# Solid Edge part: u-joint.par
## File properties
Title: Ypke
Author: Abhinav Rai
Template: normal.par
Last saved by: Cadcim
Revision: 8
Application: Solid Edge
Density: 0.0000078 kg/mm^3
Accuracy: 0.01
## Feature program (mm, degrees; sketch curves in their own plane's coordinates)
sketch for "unnamed Protrusion 1" plane through (0, 0, 0) normal (0, -1, 0) x-axis (1, 0, 0)
  line (-44.45, -33.7976) -> (-44.45, 4.3024)
  arc centre (0, 4.3024) radius 44.45 from (-44.45, 4.3024) to (44.45, 4.3024) cw
  line (44.45, 4.3024) -> (44.45, -33.7976)
  line (44.45, -33.7976) -> (25.4, -33.7976)
  line (25.4, -33.7976) -> (25.4, 4.3024)
  arc centre (0, 4.3024) radius 25.4 from (-25.4, 4.3024) to (25.4, 4.3024) cw
  line (-25.4, -33.7976) -> (-25.4, 4.3024)
  line (-44.45, -33.7976) -> (-25.4, -33.7976)
extrude "unnamed Protrusion 1" add finite 50.8 along -normal
fillet "Round_3" radius 25.4
sketch for "Hole_1" plane through (44.45, 25.4, -14.7476) normal (1, 0, 0) x-axis (0, 1, 0)
  hole centre (0, 6.35) bore radius 9.525
hole "Hole_1" diameter 19.05 through
sketch for "ExtrudedProtrusion_2" plane through (46.6729, 25.4, 119.8724) normal (0, 0, 1) x-axis (-1, 0, 0)
  circle centre (46.6729, 0) radius 17.1196
extrude "ExtrudedProtrusion_2" add  Plane_Distance = 128.27 mm
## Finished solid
Body 1: solid body, 14 faces, 30 edges, 16 vertices.
  Faces by surface: cylinder 7, plane 7
  Edges by curve: line 16, circle 13, intersection 1
Bounding box of the edges (mm): 88.900 x 50.800 x 153.670, from (-44.45, 0, -33.7976) to (44.45, 50.8, 119.8724).
Cylindrical faces by radius (mm): R9.525 x2, R17.1196 x1, R25.4 x3, R44.45 x1
Planar faces by outward normal: +x 2, +y 1, +z 1, -x 2, -y 1
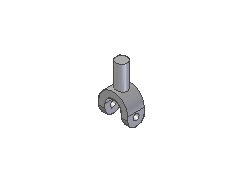
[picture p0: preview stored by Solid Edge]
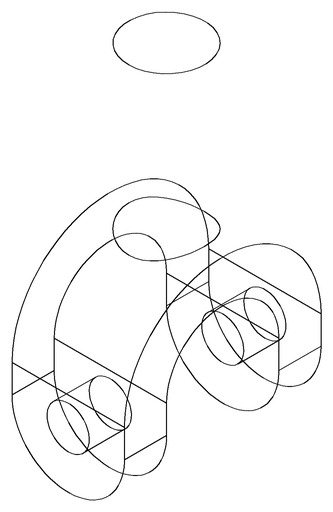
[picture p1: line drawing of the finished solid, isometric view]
